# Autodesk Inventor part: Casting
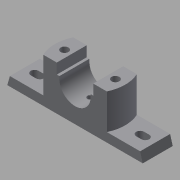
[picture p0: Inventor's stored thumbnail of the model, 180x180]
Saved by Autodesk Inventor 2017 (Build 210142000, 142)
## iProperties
Created: 2009-04
Part Number: Casting
Document SubType Name: Modeling
Designer: Sham
Density: 1 g/cm^3
Material: Generic
Appearance: Default
Author: Sham
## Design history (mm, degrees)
sketch "Sketch1"
  geometry: L1 (-104, 0)-(104, 0); L2 (-104, 0)-(-100, 14); L3 (-100, 14)-(100, 14); L4 (100, 14)-(104, 0); 1 further point
  constraints: 8 end point, 1 horizontal, 1 midpoint, 1 parallel, 1 other
  dimensions: "d0" = 208 distance of L1.start L1.end; "d1" = 104 distance of L1.end point (0, 0); "d2" = 4 horizontal distance of L1.start L2.end; "d3" = 4 horizontal distance of L1.end L3.end; "d10" = 14 distance between parallel lines of L1 L3
extrude "Extrusion1" new body sketch "Sketch1" stored distance "d4" = 46; taper "d5" = 0 deg
sketch "Sketch2"
  geometry: L1 (51.143, 46)-(148.857, 46); L2 (148.857, 0)-(51.143, 0); A1 r 54 centre (100, 23) between (51.143, 46) and (51.143, 0); A2 r 54 centre (100, 23) between (148.857, 0) and (148.857, 46)
  constraints: 4 end point, 4 point on circle, 2 centre point, 1 parallel
extrude "Extrusion2" join sketch "Sketch2" distance "d8" = 54; taper "d9" = 0 deg
sketch "Sketch3"
  geometry: L1 (-28, 68)-(-28, 52); L2 (-28, 52)-(-24, 52); L3 (28, 68)-(28, 52); L4 (28, 52)-(24, 52); L5 (-28, 68)-(28, 68); L6 (-100, 14)-(-48.857, 14) reference; L7 (0, 48)-(0, 19); L8 (48.857, 14)-(100, 14) reference; L9 (48.857, 68)-(-48.857, 68) reference; L10 (-24, 48)-(-24, 52); L11 (24, 48)-(24, 52); A1 r 24 centre (0, 48) between (-24, 48) and (24, 48); 1 further point
  constraints: 16 end point, 5 perpendicular, 2 point on circle, 2 symmetric about line, 1 centre point, 1 tangent, 1 vertical alignment, 1 other
  dimensions: "d11" = 16 distance of L1.start L1.end; "d16" = 24 radius of A1; "d17" = 16 distance of L3.start L3.end; "d52" = 56 distance between parallel lines of L1 L3; "d54" = 54 distance between parallel lines of L8 L9 (derived)
extrude "Extrusion3" cut sketch "Sketch3" distance "d18" = 54; taper "d19" = 0 deg
sketch "Sketch4"
  geometry: L1 (-23, 29)-(-15, 29); L2 (-15, 17)-(-23, 17); L3 (-185, 29)-(-177, 29); L4 (-177, 17)-(-185, 17); A1 r 6 centre (-15, 23) between (-15, 17) and (-15, 29); A2 r 6 centre (-23, 23) between (-23, 29) and (-23, 17); A3 r 6 centre (-177, 23) between (-177, 17) and (-177, 29); A4 r 6 centre (-185, 23) between (-185, 29) and (-185, 17)
  constraints: 8 end point, 8 point on circle, 8 tangent, 4 centre point, 3 parallel
  dimensions: "d20" = 8 distance of A1.centre A2.centre; "d21" = 6 radius of A1; "d24" = 6 radius of A3; "d25" = 8 distance of A4.centre A3.centre
extrude "Extrusion4" cut sketch "Sketch4" distance "d28" = 54; taper "d29" = 0 deg
sketch "Sketch5"
  geometry: L1 (208, 0)-(0, 0) reference; L2 (52, -10)-(78, -10); L3 (78, -10)-(78, -36); L4 (78, -36)-(52, -36); L5 (52, -36)-(52, -10); L6 (130, -10)-(156, -10); L7 (156, -10)-(156, -36); L8 (156, -36)-(130, -36); L9 (130, -36)-(130, -10); L10 (0, -46)-(208, -46) reference; L11 (104, -23)-(104, -46)
  constraints: 18 end point, 5 perpendicular, 4 parallel, 2 horizontal, 1 midpoint
  dimensions: "d30" = 26 distance of L2.start L2.end; "d31" = 10 distance between parallel lines of L2 L1; "d32" = 10 distance between parallel lines of L1 L6; "d65" = 26 distance between parallel lines of L3 L11; "d66" = 26 distance between parallel lines of L9 L11
extrude "Extrusion5" cut sketch "Sketch5" distance "d34" = 10; taper "d35" = 0 deg
sketch "Sketch6"
  geometry: L1 (148.857, 0)-(128, 0) reference; L2 (72, 0)-(51.143, 0) reference; L3 (0, 46)-(0, 0) reference; L4 (200, 46)-(200, 0) reference; C1 r 6 at (61, 23); C2 r 6 at (139, 23); 1 further point
  constraints: 2 centre point, 1 equal radius
  dimensions: "d36" = 12 diameter of C1; "d37" = 78 distance of C2.centre C1.centre; "d39" = 39 distance of C2.centre point (100, 23); "d58" = 39 distance of C1.centre point (100, 23); "d59" = 23 distance from line of L1 C2.centre; "d60" = 23 distance from line of L2 C1.centre; "d61" = 61 distance from line of L3 C1.centre; "d62" = 61 distance from line of L4 C2.centre (derived)
extrude "Extrusion6" cut sketch "Sketch6" stored distance "d40" = 10; taper "d41" = 0 deg
workplane "Work Plane1"
sketch "Sketch7"
  geometry: L1 (-4, 46)-(204, 46) reference; L2 (-4, 0)-(-4, 46) reference; 1 further point
  dimensions: "d43" = 23 distance from line of L1 point (100, 23); "d44" = 104 distance from line of point (100, 23) L2
hole "Hole1" sketch "Sketch7" at (100, 23) diameter "d45" = 8; stored, may be unused: countersink angle "d49" = 90 deg, drill point angle "d51" = 118 deg; dims "d46" = 6, "d47" = 8, "d48" = 16, "d50" = 8
body "Solid1"
other parameters: "d6" = 108, "d42" = -52
